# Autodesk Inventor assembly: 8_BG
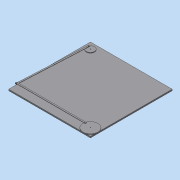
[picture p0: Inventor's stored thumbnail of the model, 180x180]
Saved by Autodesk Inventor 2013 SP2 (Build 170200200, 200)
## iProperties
Created: 2014-01
Part Number: 8_BG
Document SubType Name: Assembly
Designer: J. Palme
Author: J. Palme
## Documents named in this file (6)
- D:\Daten\Inventor\8_BG.iam
- D:\Daten\Inventor\8_Platte.ipt
- D:\Daten\Inventor\8_Antrieb-klein.ipt
- D:\Daten\Inventor\8_Antrieb-gross.ipt
- 8_Antrieb-gross.ipt
- D:\Daten\Inventor\8_Pleuel-gross.ipt
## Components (5 placed, 4 different names)
1. 8_Platte:1 — Passend:1, Passend:2, Passend:3, Passend:4, DRIVE_ME, Winkel:2
2. 8_Antrieb-klein:1 — Passend:1, Passend:2, Passend:5, Passend:6, Winkel:2
3. 8_Antrieb-gross:1 — Passend:3, Passend:4, Passend:9, DRIVE_ME
4. 8_Pleuel-gross:1 — Passend:7, Passend:8, Passend:9
5. 8_Pleuel-gross:2 — Passend:5, Passend:6, Passend:7, Passend:8
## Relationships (11: Mate 9, Angle 2)
- Passend:1 [Mate]: 8_Platte:1 ↔ 8_Antrieb-klein:1
- Passend:2 [Mate]: 8_Platte:1 ↔ 8_Antrieb-klein:1
- Passend:3 [Mate]: 8_Platte:1 ↔ 8_Antrieb-gross:1
- Passend:4 [Mate]: 8_Platte:1 ↔ 8_Antrieb-gross:1
- Passend:5 [Mate]: 8_Antrieb-klein:1 ↔ 8_Pleuel-gross:2
- Passend:6 [Mate]: 8_Antrieb-klein:1 ↔ 8_Pleuel-gross:2
- Passend:7 [Mate]: 8_Pleuel-gross:1 ↔ 8_Pleuel-gross:2
- Passend:8 [Mate]: 8_Pleuel-gross:1 ↔ 8_Pleuel-gross:2
- Passend:9 [Mate]: 8_Antrieb-gross:1 ↔ 8_Pleuel-gross:1
- DRIVE_ME [Angle]: 8_Platte:1 ↔ 8_Antrieb-gross:1
- Winkel:2 [Angle]: 8_Platte:1 ↔ 8_Antrieb-klein:1
